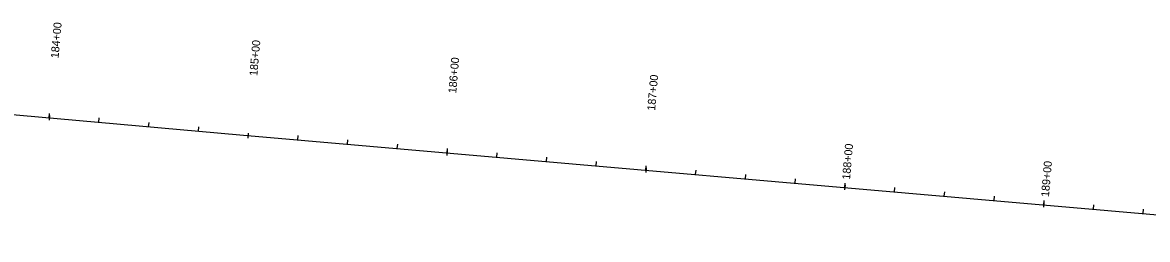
# Model space of a CAD drawing. Extents: x 20500393 to 20505339, y 7953466 to 7954298.
# Drawn here: x 20502094 to 20502657, y 7953803 to 7953912 of the extents above; entities that cross this region are included whole.
import ezdxf

# ---------------------------------------------------------------- set-up
doc = ezdxf.new("R2010")
doc.units = 0
for name, color, linetype in [('_CIVIL_CONSTRUCTION', 7, 'Continuous'), ('TextAlignmentLrg', 7, 'Continuous'), ('TextAlignmentSml', 7, 'Continuous')]:
    doc.layers.add(name, color=color, linetype=linetype)

msp = doc.modelspace()

# ---------------------------------------------------------------- linework, layer by layer
at = {"layer": '_CIVIL_CONSTRUCTION'}
for p, q in [((20501601.96, 7953909.2), (20502202.58, 7953855.42)), ((20501601.96, 7953909.2), (20502202.58, 7953855.42)), ((20502202.58, 7953855.42), (20502804.53, 7953803.04)), ((20502202.58, 7953855.42), (20502804.53, 7953803.04))]:
    msp.add_line(p, q, dxfattribs=at)
at = {"layer": 'TextAlignmentLrg'}
for p, q in [((20502107.19, 7953863.96), (20502107.38, 7953866.14)), ((20502206.9, 7953856.27), (20502206.68, 7953853.84)), ((20502306.41, 7953846.39), (20502306.6, 7953848.56)), ((20502406.04, 7953837.72), (20502406.23, 7953839.89)), ((20502505.66, 7953829.05), (20502505.85, 7953831.22)), ((20502605.28, 7953820.38), (20502605.47, 7953822.55))]:
    msp.add_line(p, q, dxfattribs=at)
at = {"layer": 'TextAlignmentSml'}
for p, q in [((20502107.3, 7953865.18), (20502107.08, 7953862.74)), ((20502132.09, 7953861.73), (20502132.28, 7953863.91)), ((20502156.99, 7953859.5), (20502157.18, 7953861.68)), ((20502181.89, 7953857.27), (20502182.08, 7953859.45)), ((20502206.9, 7953856.27), (20502206.68, 7953853.84)), ((20502231.7, 7953852.89), (20502231.89, 7953855.06)), ((20502256.6, 7953850.72), (20502256.79, 7953852.9)), ((20502281.51, 7953848.55), (20502281.7, 7953850.73)), ((20502306.52, 7953847.6), (20502306.31, 7953845.17)), ((20502331.32, 7953844.22), (20502331.51, 7953846.39)), ((20502356.23, 7953842.05), (20502356.41, 7953844.23)), ((20502381.13, 7953839.88), (20502381.32, 7953842.06)), ((20502406.14, 7953838.94), (20502405.93, 7953836.5)), ((20502430.94, 7953835.55), (20502431.13, 7953837.72)), ((20502455.85, 7953833.38), (20502456.04, 7953835.56)), ((20502480.75, 7953831.21), (20502480.94, 7953833.39)), ((20502505.77, 7953830.27), (20502505.55, 7953827.83)), ((20502530.57, 7953826.88), (20502530.76, 7953829.05)), ((20502555.47, 7953824.71), (20502555.66, 7953826.89)), ((20502580.38, 7953822.54), (20502580.57, 7953824.72)), ((20502605.39, 7953821.6), (20502605.18, 7953819.16)), ((20502630.19, 7953818.21), (20502630.38, 7953820.38)), ((20502655.1, 7953816.04), (20502655.28, 7953818.22))]:
    msp.add_line(p, q, dxfattribs=at)

# ---------------------------------------------------------------- texts
at = {"layer": 'TextAlignmentLrg'}
msp.add_text('185+00', height=4.008, rotation=85.0264, dxfattribs=at).set_placement((20502211.39, 7953884.77))
at = {"layer": 'TextAlignmentSml'}
for s, rotation, p in [('184+00', 84.8834, (20502111.86, 7953893.66)), ('185+00', 85.0264, (20502211.39, 7953884.77)), ('186+00', 85.0264, (20502311.01, 7953876.1)), ('187+00', 85.0264, (20502410.63, 7953867.43)), ('188+00', 85.0264, (20502508.24, 7953832.89)), ('189+00', 85.0264, (20502607.86, 7953824.22))]:
    msp.add_text(s, height=4.008, rotation=rotation, dxfattribs=at).set_placement(p)

doc.saveas('drawing.dxf')
